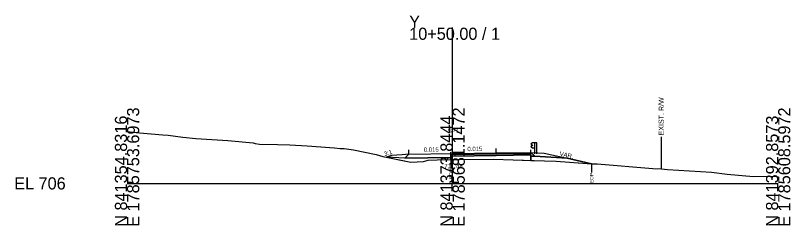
# Model space of a CAD drawing. Extents: x -26 to 153, y 990 to 3546.
# Drawn here: x -25.7 to 152.8, y 990.3 to 1038.6 of the extents above; entities that cross this region are included whole.
import ezdxf

# ---------------------------------------------------------------- set-up
doc = ezdxf.new("R2010")
doc.units = 0
for name, color, linetype in [('Exist Cross Section Cell', 7, 'Continuous'), ('Exist XS Center Line Elevation Label', 7, 'Continuous'), ('Exist XS Ground Line', 7, 'Continuous'), ('Old_Level_10', 7, 'Continuous'), ('Prop XS Ditch Slope Text', 7, 'Continuous'), ('Prop XS Earthwork Shape', 7, 'Continuous'), ('Prop XS EOT Tick Mark', 7, 'Continuous'), ('Prop XS Finish Grade', 7, 'Continuous'), ('Prop XS Finish Grade Earthwork', 7, 'Continuous'), ('Prop XS Finish Grade Pavement', 7, 'Continuous'), ('Prop XS Guardrail', 7, 'Continuous'), ('Prop XS Hydro Typical Ditch Data', 7, 'Continuous'), ('Prop XS Pvmt Edge Slope', 7, 'Continuous'), ('Prop XS SE Text', 7, 'Continuous'), ('Prop XS Subgrade Earthwork', 7, 'Continuous'), ('Scratch_Level_6', 7, 'Continuous')]:
    doc.layers.add(name, color=color, linetype=linetype)

msp = doc.modelspace()

# ---------------------------------------------------------------- linework, layer by layer
at = {"layer": 'Exist Cross Section Cell'}
for p, q in [((75, 1000), (75, 1035.85)), ((0, 1000), (75, 1000)), ((75, 1000), (150, 1000))]:
    msp.add_line(p, q, dxfattribs=at)
at = {"layer": 'Exist XS Ground Line'}
msp.add_lwpolyline([(0, 1011.95), (2.85, 1011.61), (8.27, 1011.17), (9.45, 1011.08), (12.88, 1010.66), (15.84, 1010.35), (20.76, 1010.01), (23.23, 1009.91), (29.06, 1009.31), (29.55, 1009.21), (30.51, 1009.02), (34.64, 1008.93), (37.54, 1008.89), (41.52, 1008.68), (47.81, 1008.18), (49.1, 1008.07), (49.73, 1008.05), (50.05, 1008.05), (52.19, 1007.69), (57.41, 1006.62), (58.92, 1006.22), (65.34, 1004.89), (68.28, 1005.06), (69.35, 1005.34), (71.46, 1005.43), (74.51, 1005.47), (75, 1005.48), (76.14, 1005.49), (84.42, 1005.57), (88.95, 1005.45), (96.18, 1005.19), (98.83, 1005.09), (107.09, 1004.51), (108.3, 1004.47), (121.14, 1003.42), (123.1, 1003.33), (124.48, 1003.2), (134.65, 1002.59), (138.26, 1002.1), (144.32, 1001.55), (149.1, 1001.69), (150, 1001.48)], dxfattribs=at)
at = {"layer": 'Old_Level_10'}
for p, q in [((75, 1006.87), (75, 1011.28)), ((123.05, 1010.73), (123.05, 1003.33)), ((74.63, 1005.47), (74.63, 1003.42)), ((107.03, 1004.52), (107.03, 1002.47))]:
    msp.add_line(p, q, dxfattribs=at)
at = {"layer": 'Prop XS Earthwork Shape'}
for points in [[(59.81, 1006.03), (65.34, 1004.89), (68.28, 1005.06), (69.35, 1005.34), (71.46, 1005.43), (74.51, 1005.47), (74.63, 1005.47), (74.63, 1005.94), (64.02, 1005.78)], [(93.06, 1005.3), (96.18, 1005.19), (98.83, 1005.09), (107.03, 1004.52), (101.4, 1005.78), (93.96, 1006.24), (93.06, 1006.23)]]:
    msp.add_lwpolyline(points, close=True, dxfattribs=at)
at = {"layer": 'Prop XS EOT Tick Mark'}
for p, q in [((64.95, 1006.71), (64.95, 1007.71)), ((85.05, 1007.02), (85.05, 1008.02))]:
    msp.add_line(p, q, dxfattribs=at)
at = {"layer": 'Prop XS Finish Grade'}
for p, q in [((93.06, 1007.14), (94.63, 1007.07)), ((94.63, 1007.07), (96.06, 1006.99)), ((96.06, 1006.99), (101.4, 1005.78)), ((60.95, 1006.41), (59.81, 1006.03)), ((63.38, 1006.59), (60.95, 1006.41)), ((64.95, 1006.71), (63.38, 1006.59))]:
    msp.add_line(p, q, dxfattribs=at)
at = {"layer": 'Prop XS Finish Grade Earthwork'}
msp.add_line((101.4, 1005.78), (107.03, 1004.52), dxfattribs=at)
at = {"layer": 'Prop XS Finish Grade Pavement'}
for p, q in [((75, 1006.87), (85.05, 1007.02)), ((85.05, 1007.02), (93.06, 1007.14)), ((64.95, 1006.71), (75, 1006.87))]:
    msp.add_line(p, q, dxfattribs=at)
at = {"layer": 'Prop XS Guardrail'}
for p, q in [((93.09, 1009.12), (93.06, 1009.06)), ((93.06, 1009.06), (93.09, 1009)), ((93.38, 1009.32), (93.09, 1009.12)), ((93.09, 1009), (93.38, 1008.8)), ((93.88, 1009.32), (93.38, 1009.32)), ((93.38, 1008.8), (93.38, 1008.71)), ((94.38, 1009.32), (93.88, 1009.32)), ((93.88, 1009.32), (93.88, 1006.82)), ((94.38, 1006.82), (94.38, 1009.32)), ((93.09, 1008.51), (93.06, 1008.45)), ((93.06, 1008.45), (93.09, 1008.39)), ((93.38, 1008.71), (93.09, 1008.51)), ((93.09, 1008.39), (93.38, 1008.19)), ((93.38, 1008.19), (93.88, 1008.19))]:
    msp.add_line(p, q, dxfattribs=at)
at = {"layer": 'Prop XS Hydro Typical Ditch Data'}
msp.add_line((60.95, 1006.41), (59.81, 1006.03), dxfattribs=at)
at = {"layer": 'Prop XS Pvmt Edge Slope'}
for p, q in [((93.06, 1007.14), (93.96, 1006.24)), ((64.95, 1006.71), (64.02, 1005.78))]:
    msp.add_line(p, q, dxfattribs=at)
at = {"layer": 'Prop XS Subgrade Earthwork'}
for p, q in [((64.02, 1005.78), (59.81, 1006.03)), ((64.02, 1005.78), (74.63, 1005.94)), ((74.63, 1005.94), (74.63, 1005.47)), ((93.06, 1006.23), (93.96, 1006.24)), ((93.06, 1005.3), (93.06, 1006.23)), ((93.96, 1006.24), (101.4, 1005.78))]:
    msp.add_line(p, q, dxfattribs=at)
at = {"layer": 'Scratch_Level_6'}
for p, q in [((74.63, 1005.94), (74.63, 1007.2)), ((85.05, 1006.9), (93.06, 1007.02)), ((93.06, 1007.02), (85.05, 1006.9)), ((93.06, 1006.23), (93.06, 1007.75)), ((93.06, 1006.89), (93.06, 1007.02)), ((74.63, 1006.74), (75, 1006.74)), ((75, 1006.74), (74.63, 1006.74)), ((74.63, 1006.74), (74.63, 1006.61)), ((74.63, 1006.61), (75, 1006.62)), ((74.63, 1006.61), (75, 1006.62)), ((75, 1006.62), (74.63, 1006.61)), ((74.63, 1006.61), (74.63, 1006.28)), ((74.63, 1006.28), (75.01, 1006.28)), ((74.63, 1006.28), (75.01, 1006.28)), ((75.01, 1006.28), (74.63, 1006.28)), ((74.63, 1005.94), (74.63, 1005.47)), ((75, 1006.74), (85.05, 1006.9)), ((85.05, 1006.9), (75, 1006.74)), ((75, 1006.62), (85.05, 1006.77)), ((75, 1006.62), (85.05, 1006.77)), ((85.05, 1006.77), (75, 1006.62)), ((75.01, 1006.28), (85.06, 1006.44)), ((75.01, 1006.28), (85.06, 1006.44)), ((85.06, 1006.44), (75.01, 1006.28)), ((85.05, 1006.77), (93.06, 1006.89)), ((85.05, 1006.77), (93.06, 1006.89)), ((93.06, 1006.89), (85.05, 1006.77)), ((85.06, 1006.44), (93.07, 1006.56)), ((85.06, 1006.44), (93.06, 1006.56)), ((93.06, 1006.56), (85.06, 1006.44)), ((93.06, 1006.56), (93.06, 1006.89)), ((93.06, 1006.31), (93.06, 1006.56)), ((93.06, 1006.23), (93.06, 1006.31)), ((93.06, 1005.3), (93.06, 1006.23))]:
    msp.add_line(p, q, dxfattribs=at)
for points in [[(74.63, 1006.28), (74.63, 1006.03), (74.63, 1005.94)], [(74.63, 1005.47), (75, 1005.48), (76.14, 1005.49), (84.42, 1005.57), (88.95, 1005.45), (93.06, 1005.3)]]:
    msp.add_lwpolyline(points, dxfattribs=at)

# ---------------------------------------------------------------- texts
at = {"layer": 'Exist Cross Section Cell'}
for s, p in [('Y', (65, 1035.85)), ('10+50.00 / 1', (65, 1033.05)), ('EL 706', (-26, 998.6))]:
    msp.add_text(s, height=2.8, dxfattribs=at).set_placement(p)
for s, p in [('E 1785753.6973', (2.8, 990)), ('E 1785681.1472', (77.8, 990)), ('E 1785608.5972', (152.8, 990)), ('N 841354.8316', (0, 990)), ('N 841373.8444', (75, 990)), ('N 841392.8573', (150, 990))]:
    msp.add_text(s, height=2.8, rotation=90, dxfattribs=at).set_placement(p)
at = {"layer": 'Exist XS Center Line Elevation Label'}
msp.add_text('711.48', height=1, dxfattribs=at).set_placement((73.1, 1003.48))
at = {"layer": 'Old_Level_10'}
for s, height, p in [('EXIST. R/W', 1.181, (123.64, 1011.03)), ('EOP', 0.787, (75.02, 1001.02)), ('EOP', 0.787, (107.43, 1000.07))]:
    msp.add_text(s, height=height, rotation=90, dxfattribs=at).set_placement(p)
msp.add_text('SP1', height=1, dxfattribs=at).set_placement((73.88, 1011.6))
at = {"layer": 'Prop XS Ditch Slope Text'}
for s, rotation, p in [('3:1', 18.4349, (59.36, 1006.25)), ('VAR.', 347.3228, (99.58, 1006.38))]:
    msp.add_text(s, height=1, rotation=rotation, dxfattribs=at).set_placement(p)
at = {"layer": 'Prop XS SE Text'}
for p in [(68.36, 1007.26), (78.41, 1007.42)]:
    msp.add_text('0.015', height=1, rotation=0.8785, dxfattribs=at).set_placement(p)

doc.saveas('drawing.dxf')
